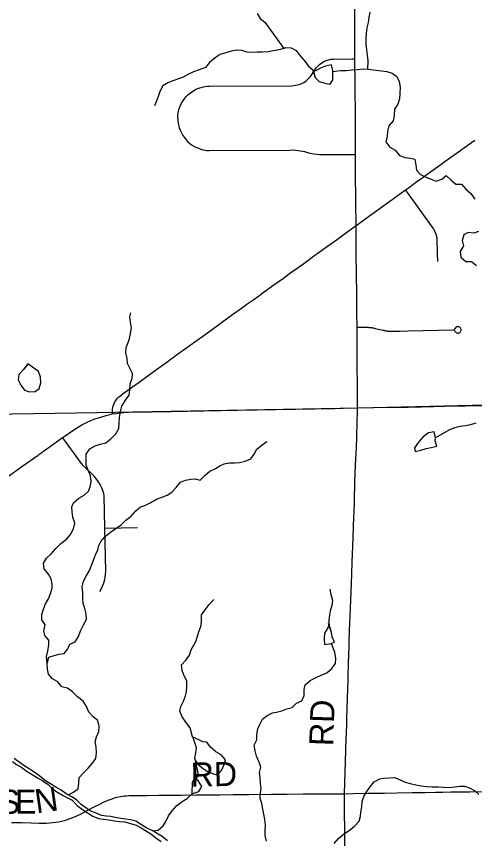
# Model space of a CAD drawing. Extents: x 0 to 34, y 0 to 22.
# Drawn here: x 3.087 to 4.171, y 18.033 to 19.975 of the extents above; entities that cross this region are included whole.
import ezdxf

# ---------------------------------------------------------------- set-up
doc = ezdxf.new("R2010")
doc.units = 0
for name, color, linetype in [('GM_X_Corporation', 7, 'Continuous'), ('GM_X_County_Road', 7, 'Continuous'), ('GM_X_County_Road_Text', 7, 'Continuous'), ('GM_X_Minor_Lake', 7, 'Continuous'), ('GM_X_Minor_River', 7, 'Continuous'), ('GM_X_State_Route', 7, 'Continuous'), ('GM_X_Township_Road', 7, 'Continuous'), ('GM_X_Township_Road_Text', 7, 'Continuous')]:
    doc.layers.add(name, color=color, linetype=linetype)

msp = doc.modelspace()

# ---------------------------------------------------------------- linework, layer by layer
at = {"layer": 'GM_X_Corporation'}
msp.add_lwpolyline([(7.9922, 20.9), (2.8099, 20.9), (2.8107, 20.774), (2.8158, 19.9868), (2.8247, 19.0323), (3.279, 19.0395), (3.3208, 19.0402), (3.8964, 19.0508), (4.1999, 19.0575), (4.5008, 19.0629), (4.7704, 19.0672), (4.9094, 19.0728), (5.4081, 19.0763), (6.7986, 19.0964), (7.9898, 19.1149), (7.9901, 19.6615), (7.9904, 20.2824), (7.9906, 20.6512)], close=True, dxfattribs=at)
msp.add_lwpolyline([(2.837, 17.9259), (2.8293, 18.7154), (2.8247, 19.0323), (3.279, 19.0395), (3.3208, 19.0402), (3.8964, 19.0508), (4.1999, 19.0575), (4.5008, 19.0629), (4.7704, 19.0672), (4.9094, 19.0728), (5.4081, 19.0763), (6.7986, 19.0964), (7.9898, 19.1149), (7.9884, 19.0254), (7.988, 19.001), (7.9901, 18.1613), (7.991, 17.7727)], dxfattribs=at)
at = {"layer": 'GM_X_County_Road'}
msp.add_lwpolyline([(3.075, 18.071), (3.0989, 18.0705), (3.1219, 18.0696), (3.1407, 18.0692), (3.1575, 18.0695), (3.1654, 18.07), (3.1726, 18.0706), (3.18, 18.0715), (3.1866, 18.0725), (3.1936, 18.0739), (3.201, 18.0757), (3.2076, 18.0776), (3.2141, 18.0799), (3.2207, 18.0825), (3.2264, 18.085), (3.2327, 18.0878), (3.2387, 18.0907), (3.2454, 18.0941), (3.2546, 18.0988), (3.271, 18.1077), (3.2855, 18.1152), (3.2944, 18.1196), (3.2997, 18.122), (3.3061, 18.1245), (3.3132, 18.127), (3.3192, 18.1289), (3.3241, 18.1302), (3.329, 18.1314), (3.3334, 18.1322), (3.3384, 18.133), (3.3428, 18.1336), (3.3476, 18.1341), (3.3529, 18.1345), (3.3605, 18.1347), (3.3785, 18.1348), (3.3962, 18.1349), (3.4242, 18.1352), (3.4463, 18.1352), (3.477, 18.1356), (3.5127, 18.1361), (3.568, 18.1363), (3.5995, 18.1366), (3.6366, 18.1369), (3.69, 18.1373), (3.7278, 18.1377), (3.7652, 18.1381), (3.7948, 18.1383), (3.8132, 18.1384), (3.8342, 18.1385), (3.8525, 18.1387), (3.8628, 18.1388), (3.8838, 18.139), (3.9185, 18.1397), (3.9578, 18.1404), (3.9872, 18.1409), (4.0222, 18.1416), (4.0536, 18.142), (4.0784, 18.1424), (4.0958, 18.1426), (4.1145, 18.1428), (4.1599, 18.1432), (4.2031, 18.1436)], dxfattribs=at)
at = {"layer": 'GM_X_Minor_Lake'}
for points in [[(3.8353, 19.8386), (3.8351, 19.8477), (3.8326, 19.861), (3.8183, 19.8581), (3.8059, 19.8533), (3.7935, 19.8459), (3.7889, 19.8483)], [(3.787, 19.8497), (3.7938, 19.8314), (3.8031, 19.8217), (3.8167, 19.8174), (3.8289, 19.8157), (3.8355, 19.8253), (3.8353, 19.8386)], [(3.7889, 19.8483), (3.7938, 19.8314), (3.8031, 19.8217), (3.8167, 19.8174), (3.8289, 19.8157), (3.8355, 19.8253), (3.8353, 19.8386)], [(3.1137, 19.1543), (3.1031, 19.1405), (3.0923, 19.1293), (3.0911, 19.1164), (3.0973, 19.1044), (3.1059, 19.0924), (3.118, 19.0884)], [(3.118, 19.0884), (3.1309, 19.0894), (3.1406, 19.096), (3.1445, 19.1094), (3.1439, 19.123), (3.1391, 19.1366), (3.1276, 19.1451), (3.1136, 19.1544)], [(3.118, 19.0884), (3.1309, 19.0894), (3.1406, 19.096), (3.1445, 19.1094), (3.1439, 19.123), (3.1391, 19.1366), (3.1276, 19.1451), (3.1137, 19.1543)], [(3.1135, 19.154), (3.1031, 19.1405), (3.0923, 19.1293), (3.0911, 19.1164), (3.0973, 19.1044), (3.1059, 19.0924), (3.118, 19.0884)], [(4.078, 18.9803), (4.0752, 18.9936), (4.062, 18.9915), (4.0493, 18.9818), (4.0378, 18.9694), (4.0286, 18.9564)], [(4.0781, 18.98), (4.0752, 18.9936), (4.062, 18.9915), (4.0493, 18.9818), (4.0378, 18.9694), (4.0286, 18.9564)], [(4.0286, 18.9564), (4.0303, 18.9473), (4.0438, 18.9502), (4.0559, 18.9546), (4.0683, 18.9567), (4.0815, 18.9599), (4.0775, 18.9724), (4.078, 18.9803)], [(4.0286, 18.9564), (4.0303, 18.9473), (4.0438, 18.9502), (4.0559, 18.9546), (4.0683, 18.9567), (4.0815, 18.9599), (4.0775, 18.9724), (4.078, 18.98)], [(3.8267, 18.5396), (3.824, 18.5305), (3.8161, 18.518), (3.8149, 18.5051), (3.8161, 18.4914), (3.8293, 18.4926)], [(3.8264, 18.5384), (3.824, 18.5305), (3.8161, 18.518), (3.8149, 18.5051), (3.8161, 18.4914), (3.8293, 18.4926)], [(3.8293, 18.4926), (3.8391, 18.4971), (3.8338, 18.5096), (3.8323, 18.5199), (3.8255, 18.5412)], [(3.8293, 18.4926), (3.8391, 18.4971), (3.8338, 18.5096), (3.8323, 18.5199), (3.8264, 18.5384)], [(3.5031, 18.2734), (3.5079, 18.2609), (3.5119, 18.2477), (3.5106, 18.2355), (3.5078, 18.223), (3.514, 18.2113), (3.526, 18.1998), (3.5382, 18.192), (3.5508, 18.1862), (3.5637, 18.1822), (3.5726, 18.1953)], [(3.5032, 18.2731), (3.5079, 18.2609), (3.5119, 18.2477), (3.5106, 18.2355), (3.5078, 18.223), (3.514, 18.2113), (3.526, 18.1998), (3.5382, 18.192), (3.5508, 18.1862), (3.5637, 18.1822), (3.5726, 18.1953)], [(3.5726, 18.1953), (3.5773, 18.2064), (3.5812, 18.219), (3.5712, 18.2305), (3.5589, 18.2379), (3.5459, 18.2491), (3.5374, 18.2603), (3.5279, 18.2616), (3.5032, 18.2731)], [(3.5726, 18.1953), (3.5773, 18.2064), (3.5812, 18.219), (3.5712, 18.2305), (3.5589, 18.2379), (3.5459, 18.2491), (3.5374, 18.2603), (3.5279, 18.2616), (3.5032, 18.2731)], [(3.5016, 18.1381), (3.5182, 18.1443), (3.5252, 18.1558), (3.5178, 18.1681)], [(3.5178, 18.1681), (3.5085, 18.1756), (3.5024, 18.1652), (3.5018, 18.1382)], [(3.5178, 18.1681), (3.5085, 18.1756), (3.5024, 18.1652), (3.5018, 18.1388)], [(3.5018, 18.1382), (3.5182, 18.1443), (3.5252, 18.1558), (3.5178, 18.1681)]]:
    msp.add_lwpolyline(points, dxfattribs=at)
at = {"layer": 'GM_X_Minor_River'}
for points in [[(3.6561, 19.9827), (3.6635, 19.9707), (3.6742, 19.9618)], [(3.9182, 19.8511), (3.9191, 19.8708), (3.9173, 19.8841), (3.916, 19.8962), (3.9142, 19.9095), (3.914, 19.9227), (3.9149, 19.9356), (3.917, 19.9486), (3.9198, 19.9608), (3.9218, 19.9733), (3.9235, 19.9851)], [(3.6742, 19.9618), (3.7196, 19.8996), (3.7075, 19.8967), (3.6943, 19.8942), (3.6823, 19.8917), (3.6687, 19.8907), (3.6558, 19.8909), (3.643, 19.8903), (3.6327, 19.8909), (3.6202, 19.8952), (3.6077, 19.8954), (3.5949, 19.8932), (3.5825, 19.8892), (3.5693, 19.8852), (3.557, 19.8774), (3.5435, 19.8665), (3.5339, 19.855), (3.5196, 19.849), (3.5057, 19.8446), (3.4937, 19.8391), (3.4817, 19.8321), (3.4701, 19.8277), (3.4569, 19.8233), (3.4449, 19.8185), (3.4329, 19.8111), (3.426, 19.7981), (3.422, 19.7859), (3.4173, 19.7736), (3.4137, 19.7641)], [(3.7196, 19.8997), (3.7241, 19.9017), (3.7366, 19.9014), (3.7488, 19.8948), (3.7581, 19.8824), (3.7689, 19.8697), (3.7774, 19.8585), (3.789, 19.8484)], [(3.8353, 19.8455), (3.8537, 19.8477), (3.8673, 19.8479), (3.8801, 19.8493), (3.8937, 19.8503), (3.9069, 19.8513), (3.9198, 19.8511)], [(3.9191, 19.8511), (3.9634, 19.8454), (3.976, 19.8411), (3.9867, 19.8333), (3.9922, 19.8213), (3.9947, 19.8084), (3.9942, 19.794), (3.9929, 19.781), (3.989, 19.7681), (3.9816, 19.7562), (3.9807, 19.7425), (3.9779, 19.7288), (3.9679, 19.7172), (3.9651, 19.7039), (3.9638, 19.6921), (3.961, 19.6788), (3.9703, 19.6668), (3.9829, 19.6594), (3.9934, 19.6471), (4.0063, 19.6424), (4.0192, 19.6407), (4.0298, 19.6379), (4.0316, 19.6242), (4.0333, 19.6118), (4.0426, 19.6017), (4.0555, 19.5958), (4.0681, 19.5907), (4.0803, 19.5864), (4.0931, 19.5912), (4.1039, 19.5993), (4.1147, 19.5893), (4.1262, 19.5792), (4.1402, 19.5791), (4.1502, 19.5671), (4.1618, 19.5571), (4.1711, 19.5436)], [(4.1804, 19.4671), (4.1687, 19.4635), (4.1558, 19.4651), (4.1453, 19.4593), (4.1414, 19.4463), (4.1443, 19.4331), (4.1366, 19.4196), (4.1383, 19.4068), (4.1502, 19.3964), (4.1638, 19.3962), (4.1753, 19.3869)], [(3.1596, 18.4464), (3.1578, 18.4631), (3.161, 18.476), (3.1638, 18.4897), (3.1635, 18.5019), (3.1539, 18.5123), (3.1514, 18.524), (3.155, 18.5378), (3.1468, 18.5494), (3.1474, 18.5619), (3.1513, 18.5749), (3.1556, 18.5875), (3.163, 18.5994), (3.1677, 18.612), (3.1716, 18.6242), (3.1718, 18.6337), (3.1689, 18.6461), (3.1627, 18.6578), (3.1523, 18.6701), (3.1509, 18.6838), (3.1579, 18.6956), (3.169, 18.7057), (3.1805, 18.718), (3.1921, 18.7296), (3.2051, 18.7401), (3.2148, 18.7513), (3.2217, 18.7643), (3.2253, 18.778), (3.2201, 18.7923), (3.2184, 18.8045), (3.2181, 18.8166), (3.2221, 18.8261), (3.2344, 18.837), (3.2475, 18.8444), (3.2572, 18.8537), (3.2616, 18.8636), (3.264, 18.8766), (3.2623, 18.8895), (3.2563, 18.903), (3.252, 18.9151), (3.2521, 18.928), (3.2515, 18.9409), (3.2607, 18.9539), (3.2731, 18.961), (3.2848, 18.9646), (3.2983, 18.9679), (3.3103, 18.9772), (3.3218, 18.9888), (3.3291, 19.0014), (3.3296, 19.0151), (3.3309, 19.028), (3.333, 19.0417), (3.3365, 19.0547), (3.3453, 19.0685), (3.3535, 19.0804), (3.3555, 19.0933), (3.356, 19.107), (3.3611, 19.1196), (3.3616, 19.1318), (3.3558, 19.143), (3.3499, 19.1555), (3.3485, 19.168), (3.3456, 19.1808), (3.3469, 19.1933), (3.3516, 19.2048), (3.3541, 19.2143), (3.3569, 19.2265), (3.3594, 19.2395), (3.3569, 19.2527), (3.3551, 19.2656), (3.3576, 19.2751)], [(4.1736, 19.0143), (4.1612, 19.0103), (4.1491, 19.0078), (4.1366, 19.0064), (4.1238, 19.0036), (4.1111, 18.9984), (4.0991, 18.9914), (4.0781, 18.98)], [(3.1596, 18.4464), (3.1635, 18.4613), (3.1759, 18.4657), (3.188, 18.4685), (3.2, 18.4703), (3.2086, 18.4807), (3.2133, 18.4921), (3.226, 18.4977), (3.2338, 18.5103), (3.2388, 18.5237), (3.2458, 18.5375), (3.2523, 18.5505), (3.2521, 18.5634), (3.2485, 18.5762), (3.2449, 18.5883), (3.2443, 18.6012), (3.2444, 18.6141), (3.2427, 18.6277), (3.2458, 18.6407), (3.2521, 18.6525), (3.2594, 18.6659), (3.2695, 18.6904), (3.2739, 18.7034), (3.2793, 18.7152), (3.2822, 18.7251), (3.2865, 18.7351), (3.2973, 18.747), (3.3096, 18.7571), (3.3223, 18.7653), (3.335, 18.7739), (3.3458, 18.7854), (3.3581, 18.7948), (3.3692, 18.8075), (3.3808, 18.8164), (3.391, 18.82), (3.403, 18.8259), (3.4183, 18.8345), (3.4296, 18.8385), (3.4439, 18.8441), (3.4547, 18.8511), (3.4651, 18.8623), (3.4751, 18.875), (3.4867, 18.8793), (3.4996, 18.8822), (3.5094, 18.8824), (3.5215, 18.8796), (3.5338, 18.8912), (3.5446, 18.9012), (3.5581, 18.9071), (3.5679, 18.9134), (3.578, 18.9181), (3.5908, 18.9206), (3.6029, 18.9205), (3.615, 18.9214), (3.6282, 18.9243), (3.6417, 18.9299), (3.6495, 18.941), (3.6553, 18.9525), (3.6684, 18.963), (3.6796, 18.9711)], [(3.8267, 18.5396), (3.827, 18.5491), (3.8286, 18.5617), (3.8303, 18.5712), (3.8339, 18.5842), (3.8352, 18.5956), (3.8316, 18.6088), (3.8294, 18.6224)], [(3.5032, 18.2731), (3.4978, 18.2945), (3.4877, 18.3076), (3.4788, 18.3203), (3.4733, 18.3335), (3.4757, 18.345), (3.4819, 18.3576), (3.4866, 18.3702), (3.4895, 18.3797), (3.4904, 18.3915), (3.4898, 18.4051), (3.4839, 18.4172), (3.4788, 18.43), (3.4778, 18.4436), (3.4878, 18.4544), (3.4967, 18.466), (3.5006, 18.4789), (3.5057, 18.4885), (3.5112, 18.4985), (3.5152, 18.5111), (3.5195, 18.524), (3.5242, 18.5363), (3.5244, 18.548), (3.5249, 18.5613), (3.5337, 18.5736), (3.543, 18.5859), (3.5537, 18.5975)], [(3.6784, 18.0264), (3.6752, 18.04), (3.675, 18.0518), (3.6759, 18.0651), (3.6745, 18.0779), (3.672, 18.0904), (3.6695, 18.1025), (3.6674, 18.1154), (3.6638, 18.1278), (3.6647, 18.1411), (3.666, 18.151), (3.6647, 18.1635), (3.6633, 18.1768), (3.6616, 18.1889), (3.6648, 18.2014), (3.6615, 18.2131), (3.6552, 18.2271), (3.652, 18.2403), (3.6495, 18.2531), (3.656, 18.2662), (3.6558, 18.2783), (3.6582, 18.292), (3.6626, 18.3019), (3.6688, 18.3146), (3.6804, 18.3235), (3.6924, 18.3298), (3.7022, 18.3318), (3.715, 18.3343), (3.727, 18.3395), (3.739, 18.3427), (3.7498, 18.3524), (3.7622, 18.3583), (3.7673, 18.3705), (3.7678, 18.3846), (3.7699, 18.3964), (3.7822, 18.4061), (3.7957, 18.4131), (3.8081, 18.4187), (3.8212, 18.4246), (3.8331, 18.4343), (3.8416, 18.4466), (3.8429, 18.4591), (3.8404, 18.4724), (3.8325, 18.4938)], [(3.2044, 18.1388), (3.2112, 18.1372), (3.2206, 18.1417), (3.2329, 18.1499), (3.2346, 18.1636), (3.2351, 18.1772), (3.2455, 18.188), (3.2566, 18.1992), (3.267, 18.2112), (3.2751, 18.2223), (3.276, 18.2352), (3.2754, 18.2493), (3.2733, 18.2617), (3.2765, 18.2732), (3.2816, 18.2858), (3.2825, 18.2987), (3.2796, 18.3116), (3.2681, 18.3205), (3.2581, 18.3313), (3.2526, 18.3448), (3.2448, 18.3576), (3.2317, 18.368), (3.2198, 18.3796), (3.2079, 18.3881), (3.1942, 18.3916), (3.1846, 18.4028), (3.172, 18.4102), (3.1627, 18.4214), (3.1602, 18.4328), (3.1596, 18.4464)], [(3.0774, 18.2151), (3.0874, 18.208), (3.1, 18.2003), (3.1127, 18.1914), (3.1245, 18.184), (3.1371, 18.1759), (3.149, 18.1693), (3.162, 18.1604), (3.1728, 18.1496), (3.1843, 18.1422), (3.1976, 18.1348), (3.2095, 18.1282), (3.219, 18.1231), (3.2306, 18.1111), (3.2432, 18.1011), (3.2677, 18.0856), (3.2814, 18.0798), (3.2928, 18.0785), (3.3057, 18.0768), (3.3186, 18.0744), (3.3307, 18.0727), (3.3432, 18.0721), (3.3569, 18.0686), (3.3699, 18.0643), (3.3824, 18.058), (3.392, 18.0521), (3.4046, 18.0436), (3.4169, 18.0347), (3.4295, 18.0262)], [(3.4443, 18.0276), (3.432, 18.0377), (3.4224, 18.0428), (3.4098, 18.0513), (3.3957, 18.0575), (3.3827, 18.0652), (3.3693, 18.0737), (3.3571, 18.0769), (3.345, 18.0786), (3.3336, 18.0803), (3.3215, 18.0828), (3.3097, 18.0848), (3.2999, 18.0858), (3.2881, 18.0875), (3.2752, 18.0926), (3.263, 18.0977), (3.2534, 18.1036), (3.2404, 18.1136), (3.2288, 18.1244), (3.2166, 18.1325), (3.2044, 18.1388), (3.1925, 18.1473), (3.1803, 18.1543), (3.1676, 18.162), (3.1535, 18.1709), (3.1412, 18.1809), (3.1289, 18.1898), (3.1171, 18.1979), (3.1048, 18.2053), (3.093, 18.2134), (3.0815, 18.2216)], [(3.5126, 18.172), (3.5167, 18.1871), (3.5103, 18.2182)], [(3.8389, 18.0209), (3.8485, 18.0328), (3.8608, 18.0429), (3.8739, 18.0518), (3.8866, 18.0623), (3.8978, 18.0735), (3.9013, 18.0857), (3.9019, 18.0952), (3.904, 18.1078), (3.9045, 18.1207), (3.9088, 18.1321), (3.9147, 18.1417), (3.9228, 18.1544), (3.9332, 18.1671), (3.9463, 18.1737), (3.9561, 18.1751), (3.9693, 18.1764), (3.9818, 18.1774), (3.9944, 18.1712), (4.0066, 18.1657), (4.0184, 18.1632), (4.0316, 18.1601), (4.0442, 18.1572), (4.0571, 18.156), (4.0707, 18.1551), (4.0843, 18.1553), (4.0976, 18.1544), (4.1104, 18.1531), (4.124, 18.1552), (4.1369, 18.1562), (4.1467, 18.1564), (4.1589, 18.1524), (4.1707, 18.1466), (4.1807, 18.1365)], [(3.4098, 18.0513), (3.4223, 18.0527), (3.4338, 18.0631), (3.4412, 18.075), (3.447, 18.0865), (3.4555, 18.098), (3.4666, 18.1111), (3.4793, 18.12), (3.4905, 18.1278), (3.5024, 18.1387)]]:
    msp.add_lwpolyline(points, dxfattribs=at)
at = {"layer": 'GM_X_State_Route'}
msp.add_line((3.3142, 19.036), (3.3223, 19.0372), dxfattribs=at)
for points in [[(4.1439, 19.6636), (4.1559, 19.6722), (4.1716, 19.6834)], [(3.4623, 19.1731), (3.498, 19.1987), (3.5441, 19.2319), (3.5904, 19.2657), (3.6092, 19.2793), (3.619, 19.2861), (3.6318, 19.2955), (3.6482, 19.3069), (3.6656, 19.3195), (3.6708, 19.3231), (3.6905, 19.3372), (3.6938, 19.3395), (3.7184, 19.3572), (3.7329, 19.3677), (3.7385, 19.3716), (3.7512, 19.3808), (3.7666, 19.3919), (3.7932, 19.4112), (3.7976, 19.4144), (3.8232, 19.4329), (3.8462, 19.4494), (3.8654, 19.4633), (3.8903, 19.4814), (4.0077, 19.5655), (4.0141, 19.5701), (4.0376, 19.5875), (4.0381, 19.5879), (4.0554, 19.6003), (4.0827, 19.6198), (4.1123, 19.641), (4.1252, 19.6503), (4.1406, 19.6613), (4.1431, 19.663), (4.1439, 19.6636)], [(3.3142, 19.036), (3.314, 19.0422), (3.3142, 19.0475), (3.3153, 19.0525), (3.3166, 19.0568), (3.3181, 19.0608), (3.3198, 19.0644), (3.3221, 19.0682), (3.3247, 19.0716), (3.3287, 19.0754), (3.3336, 19.0797), (3.3398, 19.0843), (3.3618, 19.1001), (3.3771, 19.1114), (3.413, 19.1374), (3.4456, 19.1611), (3.4536, 19.1668), (3.4566, 19.169), (3.4623, 19.1731)], [(3.3223, 19.0372), (3.3274, 19.038), (3.3412, 19.0395), (3.3517, 19.0403), (3.3616, 19.0408), (3.3793, 19.041), (3.4076, 19.0412), (3.4528, 19.0419)], [(3.4528, 19.0419), (3.4911, 19.0426), (3.611, 19.0447), (3.7469, 19.0472), (3.793, 19.0482), (3.8405, 19.0492), (3.8596, 19.0496), (3.8939, 19.0504), (3.9327, 19.0511), (3.9793, 19.0519), (3.9889, 19.0521), (3.9961, 19.0522), (4.014, 19.0525), (4.0317, 19.0528), (4.0456, 19.0531), (4.0741, 19.0537), (4.0993, 19.0542), (4.1987, 19.0561)], [(3.2126, 18.9915), (3.2206, 18.9972), (3.2313, 19.0041), (3.2417, 19.0101), (3.2526, 19.0156), (3.2632, 19.0204), (3.2748, 19.025), (3.2866, 19.0287), (3.3015, 19.0329), (3.3142, 19.036)], [(3.1471, 18.9452), (3.1488, 18.9464), (3.1511, 18.948), (3.159, 18.9536), (3.1959, 18.9801), (3.2047, 18.9858), (3.2126, 18.9915)], [(2.8325, 18.717), (2.8605, 18.7387), (2.8799, 18.7531), (2.9015, 18.7688), (2.9335, 18.792), (2.9722, 18.8199), (2.9875, 18.8309), (2.9952, 18.8364), (3.0183, 18.8531), (3.0446, 18.872), (3.0534, 18.8784), (3.0625, 18.8849), (3.0996, 18.9116), (3.0998, 18.9117), (3.1382, 18.9391), (3.1396, 18.94), (3.1471, 18.9452)]]:
    msp.add_lwpolyline(points, dxfattribs=at)
at = {"layer": 'GM_X_Township_Road'}
msp.add_line((3.2964, 18.7666), (3.3736, 18.7674), dxfattribs=at)
for points in [[(3.8903, 19.4814), (3.8899, 19.5378), (3.8897, 19.5614), (3.8894, 19.5851), (3.8893, 19.6264), (3.8892, 19.6493), (3.889, 19.7375), (3.8882, 19.8115), (3.8877, 19.875), (3.8875, 19.9329), (3.8874, 19.9648), (3.8873, 19.9785), (3.8871, 20.0349), (3.887, 20.0509), (3.8867, 20.0863), (3.8863, 20.1111), (3.8861, 20.1353), (3.886, 20.1585), (3.8858, 20.1728), (3.8855, 20.206), (3.8854, 20.2161)], [(3.4685, 19.7345), (3.4687, 19.7405), (3.4695, 19.7474), (3.4714, 19.7558), (3.4741, 19.7631), (3.4778, 19.7707), (3.4835, 19.78), (3.4886, 19.7865), (3.4927, 19.7904), (3.4986, 19.7951), (3.5041, 19.7989), (3.5102, 19.8025), (3.5139, 19.8042), (3.5187, 19.806), (3.5265, 19.8084), (3.5324, 19.8097), (3.5378, 19.8103), (3.5438, 19.8106), (3.7386, 19.8116), (3.7482, 19.8127), (3.7561, 19.8146), (3.7624, 19.8171), (3.7665, 19.8194), (3.7723, 19.8234), (3.7758, 19.8264), (3.7794, 19.83), (3.7824, 19.8334), (3.7856, 19.8379), (3.7891, 19.8428), (3.7934, 19.8499), (3.796, 19.8536), (3.7985, 19.8567), (3.804, 19.8619), (3.8095, 19.8659), (3.816, 19.8695), (3.8205, 19.8715), (3.8251, 19.8731), (3.8308, 19.8743), (3.8382, 19.8748), (3.882, 19.875), (3.8877, 19.875)], [(3.4685, 19.7345), (3.469, 19.7283), (3.4695, 19.7241), (3.4705, 19.7189), (3.4711, 19.7158), (3.4723, 19.7114), (3.4739, 19.7071), (3.4755, 19.7033), (3.4779, 19.6988), (3.4809, 19.6937), (3.4842, 19.6891), (3.4884, 19.6837), (3.4919, 19.6802), (3.4953, 19.6769), (3.5013, 19.6719), (3.5063, 19.6689), (3.5115, 19.6664), (3.5177, 19.6638), (3.5231, 19.6617), (3.5276, 19.6605), (3.5324, 19.6594), (3.5373, 19.6587), (3.5428, 19.6585), (3.7331, 19.6597), (3.7412, 19.6598), (3.7479, 19.6594), (3.7591, 19.6579), (3.7681, 19.6561), (3.7814, 19.6526), (3.7908, 19.6508), (3.7978, 19.6497), (3.8037, 19.6491), (3.8088, 19.6488), (3.8892, 19.6493)], [(4.0836, 19.3962), (4.0832, 19.4149), (4.0825, 19.4481), (4.0824, 19.449), (4.0822, 19.45), (4.0821, 19.451), (4.082, 19.4519), (4.0818, 19.4529), (4.0816, 19.4538), (4.0814, 19.4548), (4.0812, 19.4557), (4.081, 19.4567), (4.0807, 19.4576), (4.0805, 19.4585), (4.0802, 19.4595), (4.0799, 19.4604), (4.0796, 19.4613), (4.0793, 19.4622), (4.0789, 19.4631), (4.0786, 19.464), (4.0782, 19.4649), (4.0778, 19.4658), (4.0774, 19.4667), (4.077, 19.4676), (4.0766, 19.4684), (4.0761, 19.4693), (4.0756, 19.4702), (4.0752, 19.471), (4.0747, 19.4718), (4.0742, 19.4727), (4.0736, 19.4735), (4.0726, 19.475), (4.0141, 19.5562), (4.0077, 19.5655)], [(3.8939, 19.0504), (3.8937, 19.0884), (3.8936, 19.1033), (3.8935, 19.1167), (3.8934, 19.1374), (3.8933, 19.1591), (3.8932, 19.1735), (3.893, 19.2021), (3.8929, 19.2248), (3.8928, 19.2409), (3.8922, 19.2761), (3.8921, 19.2947), (3.892, 19.3196), (3.8903, 19.4145), (3.8903, 19.4814)], [(3.8928, 19.2409), (3.9189, 19.2408), (3.9205, 19.2407), (3.922, 19.2405), (3.9236, 19.2404), (3.9252, 19.2402), (3.9267, 19.24), (3.9282, 19.2398), (3.9298, 19.2395), (3.9313, 19.2392), (3.9329, 19.2389), (3.9344, 19.2386), (3.9359, 19.2382), (3.9543, 19.2341), (3.9558, 19.2337), (3.9573, 19.2334), (3.9588, 19.2331), (3.9603, 19.2328), (3.9618, 19.2326), (3.9633, 19.2323), (3.9648, 19.2321), (3.9664, 19.2319), (3.9679, 19.2318), (3.9694, 19.2317), (3.9709, 19.2316), (3.9725, 19.2315), (3.9945, 19.2319), (4.0139, 19.2326), (4.1212, 19.2347), (4.1223, 19.2341), (4.1233, 19.2329), (4.1241, 19.2316), (4.125, 19.2304), (4.1262, 19.2294), (4.1273, 19.2285), (4.1287, 19.2277), (4.1304, 19.2273), (4.132, 19.2272), (4.1338, 19.2274), (4.135, 19.2281), (4.1366, 19.2294), (4.1378, 19.2308), (4.1384, 19.2322), (4.1388, 19.2335), (4.1387, 19.2362), (4.1382, 19.2374), (4.1376, 19.2388), (4.1365, 19.2401), (4.135, 19.2411), (4.1336, 19.2417), (4.1318, 19.2421), (4.1285, 19.2417), (4.1268, 19.2406), (4.1254, 19.2393), (4.124, 19.2375), (4.1216, 19.2349)], [(3.8642, 18.0093), (3.8638, 18.0565), (3.8632, 18.092), (3.8629, 18.1202), (3.8628, 18.1388), (3.8652, 18.2145), (3.8672, 18.2706), (3.8674, 18.2793), (3.8686, 18.305), (3.8688, 18.3149), (3.8695, 18.3409), (3.8717, 18.4083), (3.8718, 18.415), (3.8727, 18.4468), (3.8733, 18.4676), (3.8739, 18.4841), (3.8743, 18.4971), (3.8752, 18.5229), (3.876, 18.5428), (3.8766, 18.5583), (3.8782, 18.5964), (3.8805, 18.6567), (3.8813, 18.6868), (3.8828, 18.7234), (3.8836, 18.7437), (3.8853, 18.7948), (3.8856, 18.8026), (3.8866, 18.8304), (3.8869, 18.8402), (3.8875, 18.8662), (3.8878, 18.8776), (3.8894, 18.9144), (3.8905, 18.9435), (3.8911, 18.9545), (3.8938, 19.0444), (3.8939, 19.0504)], [(3.2846, 18.6167), (3.2887, 18.6251), (3.294, 18.6374), (3.2961, 18.6452), (3.2969, 18.6495), (3.2976, 18.6565), (3.2981, 18.6644), (3.2964, 18.7666), (3.2943, 18.8436), (3.2937, 18.8485), (3.2924, 18.8531), (3.2883, 18.8634), (3.2849, 18.8695), (3.2813, 18.8754), (3.277, 18.8816), (3.2714, 18.8881), (3.2453, 18.9133), (3.2411, 18.9187), (3.2027, 18.971), (3.1959, 18.9801)]]:
    msp.add_lwpolyline(points, dxfattribs=at)

# ---------------------------------------------------------------- texts
at = {"layer": 'GM_X_County_Road_Text'}
for s, height, rotation, p in [('RD', 0.05682, 0.9902, (3.4996, 18.1554)), ('S', 0.0568, 0.0998, (3.045, 18.0912)), ('E', 0.0568, 0.3097, (3.0835, 18.0913)), ('N', 0.0568, 8.105, (3.1344, 18.0921))]:
    msp.add_text(s, height=height, rotation=rotation, dxfattribs=at).set_placement(p)
at = {"layer": 'GM_X_Township_Road_Text'}
msp.add_text('RD', height=0.05682, rotation=88.0262, dxfattribs=at).set_placement((3.8362, 18.2505))

doc.saveas('drawing.dxf')
